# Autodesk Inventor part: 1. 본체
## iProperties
Created: 2015-06
Part Number: 1. 본체
Document SubType Name: Modeling
Designer: elite
Density: 2.71 g/cm^3
Material: 알루미늄-6061
Mass: 3262.96 g
Surface Area: 2330.61 cm^2
Volume: 1204.04 cm^3
Author: elite
